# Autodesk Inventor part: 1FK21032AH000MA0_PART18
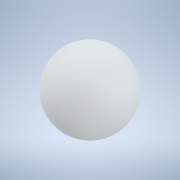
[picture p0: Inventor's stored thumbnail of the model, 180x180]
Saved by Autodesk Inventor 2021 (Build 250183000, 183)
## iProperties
Created: 2025-04
Part Number: 1FK21032AH000MA0_PART18
Material: Generic
Catalog Web Link: www.3dfindit.com
Description: -Servo synchronous motor
Document SubType Name: Modeling
Designer: psAdmin
Mass: 0.113097 g
Surface Area: 1.13097 cm^2
Volume: 0.113097 cm^3
Density: 1 g/cm^3
Appearance: PSOLRGB-212-217-219
Category: PARTsolutions
Title: 1FK21032AH000MA0_PART18
Author: Cadenas PARTsolutions
Comments: Servo synchronous motor
Sending System: PARTsolutions
Preprocessor: ST-DEVELOPER v19.3
PSOL_IDENT_0: {$CADENAS_DATA/23d-libs/siemens_ag/_cat_/45/10/1fk21032ah000ma0.prj},216 {VTYP=3D},{NB=1FK21032AH000
PSOL_IDENT_1: MA0_PART18},{LINA=1FK21032AH000MA0_PART18},{NN=1FK21032AH000MA0_PART18},{NOPRJ=TRUE},{DATE=19.08.202
PSOL_IDENT_2: 5 14:00:35},{GEOMDATE=30.07.2025 02:02:03},{VERSION=},{LINEID=10},{WBVAR=},{WBNUMERIC=}  {NB=1FK2103
PSOL_IDENT_3: 2AH000MA0_PART18},{LINA=1FK21032AH000MA0_PART18},{KT=DUMMY},{PREVIEW=../../../_pool_/14/8e/p_d211_xx
PSOL_IDENT_4: _00426j.png},{DESCSHORT=SIMOTICS S-1FK2 HD, SINAMICS S210 3AC 400V-480V, 0.59 Nm, 4500 rpm},{DESCLON
PSOL_IDENT_5: G=SIMOTICS S-1FK2 HD servo motor M0=0.64 Nm; PN = 0.28 kW at nN=4500 rpm (380-480 V); PN = 0.167 kW
PSOL_IDENT_6: at nN=2500 rpm (200-240 V); degree of protection IP64; cylindrical shaft D14 x 30 mm; absolute encod
PSOL_IDENT_7: er 22-bit + 12-bit multiturn (encoder AM22DQC); with OCC interface; plug size M17, rotatable; SIMOTI
PSOL_IDENT_8: CS S-1FK2 servomotorfor a wide range of uses in industrial environments. SIMOTICS S‑1FK2 servomotors
PSOL_IDENT_9: are compact synchronous motors with a high dynamic performance that set themselves apart as a resul
PSOL_IDENT_10: t of their high power density, degree of protection and overload capability. The motors are availabl
PSOL_IDENT_11: e in two variants: as High Dynamic variant (highest dynamic performance as a result of the low intri
PSOL_IDENT_12: nsic moment of inertia for applications demanding a high dynamic performance with low moved masses)
PSOL_IDENT_13: - and as Compact variant (precise and stable closed-loop control for medium up to large moved masses
PSOL_IDENT_14: as a result of a medium intrinsic moment of inertia). SIMOTICSS‑1FK2 servomotors fully exploit thei
PSOL_IDENT_15: r strengths in a system with the SINAMICSS210 frequency converter and simple connection using the on
PSOL_IDENT_16: e cable connection (OCC). Advantages include the short control and positioning times, fast and preci
PSOL_IDENT_17: se correction of disturbing quantities as well as stable control with a high dynamic performance. Th
PSOL_IDENT_18: e servo motors can be configured to address a wide range of requirements. For example with and witho
PSOL_IDENT_19: ut holding brake, IP64 or IP65 degree of protection, singleturn or multiturn absolute encoders - to
PSOL_IDENT_20: name just a few. Further, the servomotors are available in different shaft heights extending from 20
PSOL_IDENT_21: to 100. A shaft sealing ring is available to achieve an IP65 degree of protection and for subsequen
PSOL_IDENT_22: t mounting at the motor or as spare part. SIMOTICS - the optimum motor for each and every motion con
PSOL_IDENT_23: trol application.},{INTNO=195125335004},{SUPPLIERALTNO=1FK2103-2AH00-0MA0},{MANUID=1FK21032AH000MA0}
PSOL_IDENT_24: ,{MANUNAME=Siemens},{MANUTYPEDESC=SYNCHRONOUS MOTOR 1FK2 HD 0,64 NM},{AAU732=SIMOTICS},{AAO057=S-1FK
PSOL_IDENT_25: 2},{AAU734=SIMOTICS S-1FK2 HD servo motor M0=0.64 Nm; PN = 0.28 kW at nN=4500 rpm (380-480 V); PN =
PSOL_IDENT_26: 0.167 kW at nN=2500 rpm (200-240 V); degree of protection IP64; cylindrical shaft D14 x 30 mm; absol
PSOL_IDENT_27: ute encoder 22-bit + 12-bit multiturn (encoder AM22DQC); with OCC interface; plug size M17, rotatabl
PSOL_IDENT_28: e;},{AAW338=SYNCHRONOUS MOTOR 1FK2 HD 0,64 NM},{AAO742=SIMOTICS},{AAO663=4034106444624},{NOCUPEROU=1
PSOL_IDENT_29: },{PRICEQUANTITY=1},{QUANTITYMIN=1},{QUANTITYINT=1},{CTN=85015100},{COO=RO},{AAO676=1FK2103-2AH00-0M
PSOL_IDENT_30: A0},{AAO677=Siemens AG},{ORDERUNIT=C62},{CONTENTUNIT=C62}
NB: 1FK21032AH000MA0_PART18
NT: Servo synchronous motor
NBSYN: $MANUID._PART18
LINA: 1FK21032AH000MA0_PART18
CATALOG: SIEMENS
PREVIEW: ../../../_pool_/14/8e/p_d211_xx_00426j.png
DESCSHORT: SIMOTICS S-1FK2 HD, SINAMICS S210 3AC 400V-480V, 0.59 Nm, 4500 rpm
DESCLONG: SIMOTICS S-1FK2 HD servo motor M0=0.64 Nm; PN = 0.28 kW at nN=4500 rpm (380-480 V); PN = 0.167 kW at nN=2500 rpm (200-240 V); degree of protection IP64; cylindr
INTNO: 195125335004
SUPPLIERALTNO: 1FK2103-2AH00-0MA0
MANUID: 1FK21032AH000MA0
MANUNAME: Siemens
MANUTYPEDESC: SYNCHRONOUS MOTOR 1FK2 HD 0,64 NM
AAU732: SIMOTICS
AAO057: S-1FK2
AAU734: SIMOTICS S-1FK2 HD servo motor M0=0.64 Nm; PN = 0.28 kW at nN=4500 rpm (380-480 V); PN = 0.167 kW at nN=2500 rpm (200-240 V); degree of protection IP64; cylindr
AAW338: SYNCHRONOUS MOTOR 1FK2 HD 0,64 NM
AAO742: SIMOTICS
AAO663: 4034106444624.0
NOCUPEROU: 1
PRICEQUANTITY: 1
QUANTITYMIN: 1
QUANTITYINT: 1
CTN: 85015100
COO: RO
ARTICLENO: 1FK21032AH000MA0_PART18
BOMINFO: 1FK21032AH000MA0_PART18
CREATOR: CADENAS GmbH
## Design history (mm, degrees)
feature "2025_04_17_15_00_20_0760"
body "Solid1"
